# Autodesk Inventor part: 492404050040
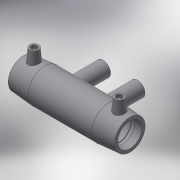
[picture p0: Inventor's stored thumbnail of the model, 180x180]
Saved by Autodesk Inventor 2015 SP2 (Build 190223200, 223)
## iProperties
Created: 2017-06
Part Number: 492404050040
Material: Generic
Description: PLASSON REDUCING TEE WITH TWO OUTLETS 50X40X40X50
Document SubType Name: Modeling
Designer: KIM
Mass: 57.3761 g
Surface Area: 241.06 cm^2
Volume: 57.3761 cm^3
Density: 1 g/cm^3
Appearance: Default
Author: KIM
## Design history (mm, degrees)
derived "492404.ipt"
feature "Solid1::492404.ipt"
tag "TaggingFeature1"
body "Solid1"
other parameters: "d0" = 195, "d2" = 68, "d3" = 49, "d4" = 39, "d5" = 61.2, "d6" = 47.5, "d8" = 168 deg, "d10" = 19.6, "d11" = 6.53333, "d23" = 68, "d29" = 51, "d30" = 15, "d31" = 78, "d34" = 5 deg, "d41" = 4, "d42" = 14, "d43" = 0, "d48" = -89, "d51" = 0, "d62" = 89, "d74" = -89, "d85" = 65, "d86" = 32.5, "d87" = 32, "d88" = 32, "d90" = 0, "d91" = 3, "d92" = 0, "L_" = 195, "L_1" = 49, "D_" = 68, "A_" = 51, "d_2" = 12, "H_" = 89, "L_2" = 65
